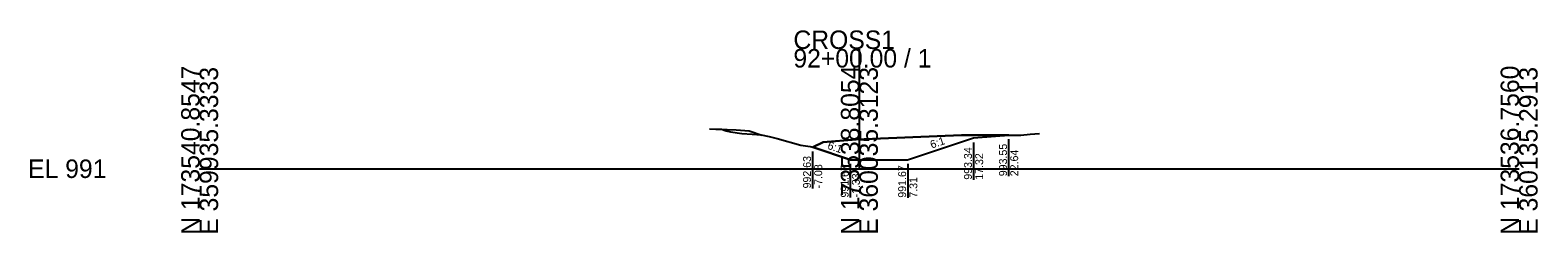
# Model space of a CAD drawing. Extents: x -26 to 1403, y -10 to 11027.
# Drawn here: x -25.7 to 202.8, y 6990.3 to 7021 of the extents above; entities that cross this region are included whole.
import ezdxf

# ---------------------------------------------------------------- set-up
doc = ezdxf.new("R2010")
doc.units = 0
for name, color, linetype in [('Default', 7, 'Continuous'), ('P_E_XS_Ground', 7, 'Continuous'), ('P_XS', 7, 'Continuous'), ('P_XS_EAR_CommonGrnd', 7, 'Continuous'), ('P_XS_Lane', 7, 'Continuous'), ('P_XS_Rock', 7, 'Continuous')]:
    doc.layers.add(name, color=color, linetype=linetype)

msp = doc.modelspace()

# ---------------------------------------------------------------- linework, layer by layer
at = {"layer": 'Default'}
for p, q in [((100, 7000), (100, 7018.12)), ((0, 7000), (100, 7000)), ((100, 7000), (200, 7000))]:
    msp.add_line(p, q, dxfattribs=at)
at = {"layer": 'P_E_XS_Ground'}
for p, q in [((77.26, 7006.04), (78.22, 7005.99)), ((78.22, 7005.99), (79.11, 7005.98)), ((79.11, 7005.98), (79.79, 7005.75)), ((79.79, 7005.75), (80.47, 7005.57)), ((80.47, 7005.57), (82.2, 7005.33)), ((82.2, 7005.33), (83.76, 7005.22)), ((83.76, 7005.22), (85.1, 7005.11)), ((85.1, 7005.11), (86.33, 7004.89)), ((86.33, 7004.89), (87.53, 7004.56)), ((87.53, 7004.56), (91.15, 7003.59)), ((99.5, 7004.44), (115.5, 7005.08)), ((115.5, 7005.08), (120.5, 7005.09)), ((120.5, 7005.09), (124.46, 7005.1)), ((124.46, 7005.1), (125.9, 7005.22)), ((125.9, 7005.22), (127.32, 7005.31)), ((91.15, 7003.59), (92.55, 7003.37)), ((92.55, 7003.37), (92.92, 7003.26)), ((92.92, 7003.26), (94.5, 7004.04)), ((94.5, 7004.04), (99.5, 7004.44))]:
    msp.add_line(p, q, dxfattribs=at)
at = {"layer": 'P_XS'}
for p, q in [((77.3, 7006.04), (81.3, 7005.88)), ((81.3, 7005.88), (83.3, 7005.72)), ((83.3, 7005.72), (85.2, 7005.09))]:
    msp.add_line(p, q, dxfattribs=at)
at = {"layer": 'P_XS_EAR_CommonGrnd'}
msp.add_lwpolyline([(117.32, 7004.67), (122.64, 7005.1), (120.5, 7005.09), (115.5, 7005.08), (99.5, 7004.44), (94.5, 7004.04), (92.92, 7003.26), (98.67, 7001.34), (107.31, 7001.34)], close=True, dxfattribs=at)
at = {"layer": 'P_XS_Lane'}
for p, q in [((107.31, 7001.34), (117.32, 7004.67)), ((117.32, 7004.67), (122.64, 7005.1)), ((98.67, 7001.34), (92.92, 7003.26)), ((98.67, 7001.34), (107.31, 7001.34))]:
    msp.add_line(p, q, dxfattribs=at)
at = {"layer": 'P_XS_Rock'}
for p, q in [((92.91, 7002.63), (92.91, 6997.02)), ((117.31, 7003.95), (117.31, 6998.34)), ((122.62, 7004.48), (122.62, 6998.87)), ((98.62, 7000.76), (98.62, 6995.64)), ((107.33, 7000.74), (107.33, 6995.61))]:
    msp.add_line(p, q, dxfattribs=at)

# ---------------------------------------------------------------- texts
at = {"layer": 'Default'}
for s, p in [('CROSS1', (90, 7018.12)), ('92+00.00 / 1', (90, 7015.32)), ('EL 991', (-26, 6998.6))]:
    msp.add_text(s, height=2.8, dxfattribs=at).set_placement(p)
for s, p in [('N 173540.8547', (0, 6990)), ('E 359935.3333', (2.8, 6990)), ('N 173538.8054', (100, 6990)), ('E 360035.3123', (102.8, 6990)), ('N 173536.7560', (200, 6990)), ('E 360135.2913', (202.8, 6990))]:
    msp.add_text(s, height=2.8, rotation=90, dxfattribs=at).set_placement(p)
at = {"layer": 'P_XS_Rock'}
for s, rotation, p in [('6:1', 18.4349, (110.96, 7003.04)), ('6:1', 341.5651, (95.07, 7003.04)), ('993.34', 90, (117.06, 6998.34)), ('17.32', 90, (118.76, 6998.34)), ('993.55', 90, (122.37, 6998.87)), ('22.64', 90, (124.07, 6998.87)), ('992.63', 90, (92.66, 6997.02)), ('-7.08', 90, (94.36, 6997.02)), ('991.67', 90, (98.37, 6995.64)), ('991.67', 90, (107.08, 6995.62)), ('-1.33', 90, (100.07, 6995.64)), ('7.31', 90, (108.78, 6995.62))]:
    msp.add_text(s, height=1.2, rotation=rotation, dxfattribs=at).set_placement(p)

doc.saveas('drawing.dxf')
